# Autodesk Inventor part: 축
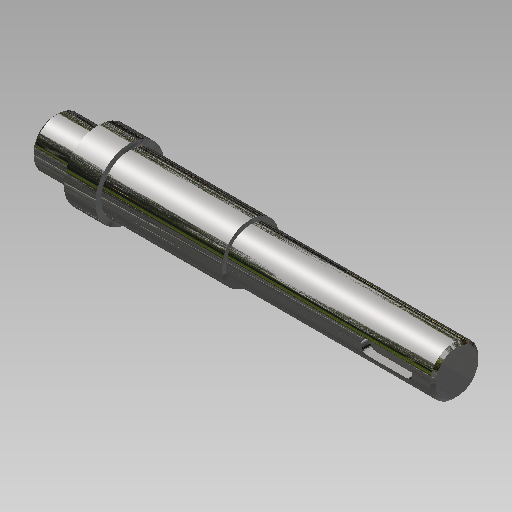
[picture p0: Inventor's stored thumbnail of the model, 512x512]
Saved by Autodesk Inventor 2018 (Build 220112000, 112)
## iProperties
Created: 2015-09
Part Number: 축
Material: 강철, 연강
Document SubType Name: Modeling
Designer: mduedu
Density: 7.86 g/cm^3
Mass: 263.424 g
Surface Area: 86.4309 cm^2
Volume: 33.5145 cm^3
Appearance: 반광택
Author: mduedu
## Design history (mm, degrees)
sketch "스케치1"
  geometry: L1 (-70, 0)-(70, 0); L2 (-70, 0)-(-70, 8.5); L3 (-70, 8.5)-(-55, 8.5); L4 (-55, 8.5)-(-55, 12); L5 (-55, 12)-(-44, 12); L6 (-44, 12)-(-44, 10); L7 (-44, 10)-(-2, 10); L8 (-2, 10)-(-2, 8.5); L9 (-2, 8.5)-(70, 8.5); L10 (70, 8.5)-(70, 0); 2 further points
  constraints: 20 end point, 5 parallel, 2 horizontal, 2 perpendicular, 1 coincident, 1 midpoint, 1 vertical
  dimensions: "d0" = 140 distance of L1.start L1.end; "d2" = 11 distance of L4.end L5.end; "d3" = 42 distance of L6.end L7.end; "d4" = 72 distance of L8.end L9.end; "d5" = 17 diameter of L3 L1; "d6" = 17 diameter of L9 L1; "d7" = 20 diameter of L7 L1; "d8" = 24 diameter of L5 L1
revolve "회전1" sketch "스케치1" stored, may be unused: angle "d9" = 90 deg
node "작업 평면1"
sketch "스케치2"
  geometry: L1 (13.5, 2.5)-(26.5, 2.5); L2 (26.5, -2.5)-(13.5, -2.5); L3 (13.5, 2.5)-(26.5, -2.5); L4 (26.5, 2.5)-(13.5, -2.5); L5 (36, -8.5)-(36, 8.5) reference; A1 r 2.5 centre (13.5, 0) between (13.5, 2.5) and (13.5, -2.5); A2 r 2.5 centre (26.5, 0) between (26.5, -2.5) and (26.5, 2.5); 2 further points
  constraints: 8 end point, 4 point on circle, 4 tangent, 2 centre point, 2 midpoint, 1 horizontal, 1 horizontal alignment, 1 parallel
  dimensions: "d10" = 18 dimension on A2 A1; "d12" = 7 distance edge to line of A2 L5; "d13" = 5 distance between parallel lines of L2 L1
extrude "돌출1" cut sketch "스케치2" distance "d14" = 3; taper "d15" = 0 deg
node "작업 평면2"
sketch "스케치4"
  geometry: L1 (7, -3)-(-9, -3); L2 (-9, 3)-(7, 3); L3 (-21, 10)-(-21, -10) reference; A1 r 3 centre (-9, 0) between (-9, 3) and (-9, -3); A2 r 3 centre (7, 0) between (7, -3) and (7, 3); 1 further point
  constraints: 4 end point, 4 point on circle, 4 tangent, 2 centre point, 1 horizontal, 1 horizontal alignment, 1 parallel
  dimensions: "d16" = 22 dimension on A1 A2; "d18" = 6 distance between parallel lines of L2 L1; "d19" = 9 distance edge to line of A1 L3
extrude "돌출2" cut sketch "스케치4" distance "d20" = 3.5; taper "d21" = 0 deg
sketch "스케치5"
  geometry: L1 (-2, 8.5)-(70, 8.5) reference; L2 (-2, -8.5)-(70, -8.5) reference; L3 (43, 8.5)-(43, -8.5); L4 (43, -6.5)-(41, -8.5); L5 (43, -8.5)-(41, -8.5); L6 (43, -8.5)-(43, -6.5); L7 (-2, -10)-(-2, 10) reference; 1 further point
  constraints: 8 end point, 4 point on line, 1 collinear, 1 perpendicular
  dimensions: "d22" = 4 diameter of L4.end L3; "d24" = 45 deg angle of L3 L4; "d26" = 45 distance between parallel lines of L3 L7
revolve "회전2" sketch "스케치5" stored, may be unused: angle "d27" = 90 deg
chamfer "모따기1" distance "d28" = 1; stored, may be unused: second distance "d29" = 2, angle "d30" = 45 deg
sketch "스케치6"
  geometry: L1 (43, -6.5)-(41, -8.5) reference; L2 (43, -6.5)-(45, -8.5) reference; 2 further points
  constraints: 1 coincident
node "솔리드1"
